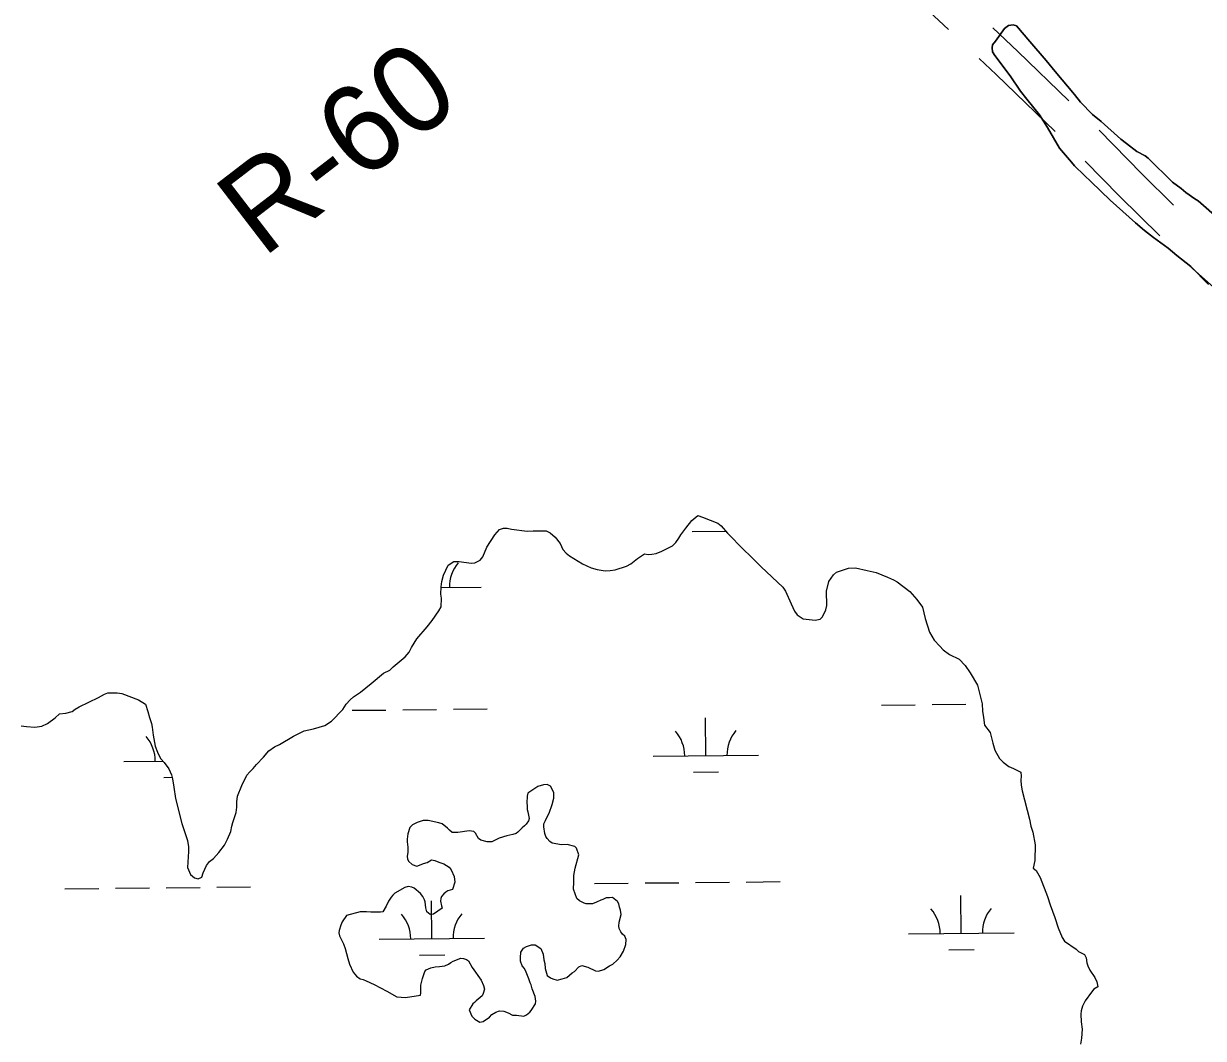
# Model space of a CAD drawing. Extents: x 3146026 to 3183936, y 897894 to 923344.
# Drawn here: x 3169411 to 3170529, y 912955 to 913917 of the extents above; entities that cross this region are included whole.
import ezdxf

# ---------------------------------------------------------------- set-up
doc = ezdxf.new("R2010")
doc.units = 0
for name, color, linetype in [('V-RIVR-RANG-IDEN', 7, 'Continuous'), ('V-ROAD-CNTR', 7, 'Continuous'), ('V-SITE-VEGE', 7, 'Continuous'), ('V-WETL-SWMP', 7, 'Continuous')]:
    doc.layers.add(name, color=color, linetype=linetype)

msp = doc.modelspace()

# ---------------------------------------------------------------- linework, layer by layer
at = {"layer": 'V-ROAD-CNTR'}
for points in [[(3170287.4, 913911.6), (3170242.1, 913954.3), (3170215.6, 913981.2)], [(3170401.7, 913844.1), (3170353.3, 913890.7), (3170329.4, 913913.2)], [(3170388.7, 913815), (3170332.6, 913869), (3170316.5, 913884.1)], [(3170500.8, 913745.2), (3170470.8, 913774.9), (3170430.2, 913816.1)], [(3170487.7, 913716), (3170449.5, 913753.7), (3170417, 913786.7)], [(3170590.8, 913621.4), (3170580.8, 913630.1), (3170519.2, 913684.7), (3170516.1, 913687.8)]]:
    msp.add_lwpolyline(points, dxfattribs=at)
at = {"layer": 'V-SITE-VEGE'}
for points in [[(3170534, 913670), (3170517.2, 913686.8), (3170503.9, 913697.3), (3170495.7, 913704.3), (3170482, 913714.4), (3170473.4, 913721.1), (3170464.8, 913728.5), (3170440.9, 913749.9), (3170422.9, 913767.1), (3170416.2, 913773.7), (3170406.8, 913782.3), (3170404.1, 913785.8), (3170392.8, 913799.1), (3170381.4, 913818.6), (3170373.9, 913830.7), (3170361.8, 913845.5), (3170355.9, 913853.3), (3170346.1, 913867.7), (3170331.3, 913886.9), (3170329.3, 913890.4), (3170328.9, 913894.3), (3170329.3, 913897), (3170332, 913900.5), (3170340.6, 913912.7), (3170344.5, 913915.4), (3170348.8, 913916.2), (3170351.9, 913915), (3170364.5, 913900.2), (3170380.1, 913882.2), (3170388.7, 913871.7), (3170407.1, 913849.9), (3170412.6, 913842.8), (3170424, 913831.1), (3170432.2, 913824.5), (3170450.9, 913807.7), (3170456.4, 913803.5), (3170466.2, 913796.1), (3170474, 913791.8), (3170476.8, 913789.8), (3170499.9, 913766.8), (3170508.1, 913761), (3170512.4, 913757.1), (3170521, 913751.2), (3170524.1, 913749.3), (3170544.8, 913731.3)], [(3170544.8, 913731.3), (3170524.1, 913749.3), (3170521, 913751.2), (3170512.4, 913757.1), (3170508.1, 913761), (3170499.9, 913766.8), (3170476.8, 913789.8), (3170474, 913791.8), (3170466.2, 913796.1), (3170456.4, 913803.5), (3170450.9, 913807.7), (3170432.2, 913824.5), (3170424, 913831.1), (3170412.6, 913842.8), (3170407.1, 913849.9), (3170388.7, 913871.7), (3170380.1, 913882.2), (3170364.5, 913900.2), (3170351.9, 913915), (3170348.8, 913916.2), (3170344.5, 913915.4), (3170340.6, 913912.7), (3170332, 913900.5), (3170329.3, 913897), (3170328.9, 913894.3), (3170329.3, 913890.4), (3170331.3, 913886.9), (3170346.1, 913867.7), (3170355.9, 913853.3), (3170361.8, 913845.5), (3170373.9, 913830.7), (3170381.4, 913818.6), (3170392.8, 913799.1), (3170404.1, 913785.8), (3170406.8, 913782.3), (3170416.2, 913773.7), (3170422.9, 913767.1), (3170440.9, 913749.9), (3170464.8, 913728.5), (3170473.4, 913721.1), (3170482, 913714.4), (3170495.7, 913704.3), (3170503.9, 913697.3), (3170517.2, 913686.8), (3170534, 913670)], [(3169969, 913088.8), (3169966, 913088.5), (3169963.1, 913088.5), (3169959.8, 913086.8), (3169957.9, 913086.2), (3169953.9, 913084.2), (3169950, 913082.9), (3169944.1, 913082.9), (3169942.2, 913083.5), (3169937.6, 913085.5), (3169935, 913087.7), (3169932, 913096.6), (3169932.3, 913103.4), (3169932.3, 913109.7), (3169933.6, 913116.5), (3169937.2, 913129.3), (3169934.9, 913135.5), (3169933.2, 913137.1), (3169926.1, 913139.1), (3169920.5, 913138.7), (3169911.7, 913140.4), (3169909.4, 913141.7), (3169907.1, 913144.6), (3169905.8, 913146.6), (3169904.8, 913149.5), (3169903.8, 913155.7), (3169903.8, 913158.7), (3169905.4, 913161.6), (3169906.4, 913163.9), (3169909, 913168.8), (3169911.9, 913177), (3169913.2, 913182.9), (3169913.5, 913188.4), (3169910.3, 913194.3), (3169907, 913196), (3169903.7, 913195.6), (3169898.2, 913194), (3169888.7, 913187.8), (3169888, 913184.8), (3169887.7, 913178.6), (3169888, 913175.6), (3169888.1, 913172.1), (3169888.7, 913170.1), (3169890, 913163.5), (3169889.4, 913161.3), (3169887.1, 913158.3), (3169885.5, 913156.7), (3169883.2, 913154.7), (3169879.3, 913150.8), (3169877.6, 913149.5), (3169874.4, 913148.5), (3169868.8, 913147.2), (3169861.6, 913144.9), (3169854.7, 913141.6), (3169850.2, 913141.6), (3169844, 913143.2), (3169842, 913144.8), (3169839, 913149.7), (3169837.4, 913151.4), (3169833.1, 913152), (3169822.4, 913150.4), (3169817.1, 913150.3), (3169814.5, 913152.6), (3169812.5, 913154.6), (3169807.6, 913158.5), (3169804.3, 913159.5), (3169794.2, 913161.7), (3169789.6, 913161.7), (3169783.7, 913159.8), (3169779.2, 913157.5), (3169776.9, 913155.2), (3169774.9, 913149), (3169774.3, 913144.1), (3169774.3, 913141.4), (3169775, 913136.5), (3169775, 913131.6), (3169774.3, 913127.7), (3169774.6, 913125.4), (3169775.6, 913123.1), (3169778.9, 913119.9), (3169783.5, 913118.6), (3169787.7, 913119.9), (3169789.7, 913120.9), (3169793.3, 913121.8), (3169797.5, 913124.5), (3169800.5, 913123.8), (3169804.4, 913122.2), (3169809, 913120.6), (3169814.2, 913117.6), (3169815.9, 913115), (3169818.8, 913108.8), (3169819.5, 913103.3), (3169817.2, 913096.4), (3169813, 913095.1), (3169811, 913093.7), (3169809, 913092.1), (3169806.8, 913089.8), (3169806.1, 913087.9), (3169805.8, 913085.2), (3169806.8, 913080.7), (3169807.4, 913078.7)], [(3169807.4, 913078.7), (3169799.3, 913072.8), (3169796, 913072.5), (3169793, 913075.1), (3169792.1, 913079), (3169791.4, 913084.6), (3169790.7, 913086.5), (3169789.1, 913089.8), (3169786.8, 913092.7), (3169780.9, 913097.6), (3169778.6, 913098.6), (3169775.3, 913099.2), (3169772.1, 913098.3), (3169762.6, 913093), (3169760.6, 913091), (3169759, 913089.1), (3169756.7, 913085.2), (3169754.4, 913080.6), (3169751.2, 913075.3), (3169748.9, 913075), (3169746.3, 913075), (3169739.7, 913075), (3169735.8, 913075.3), (3169729.6, 913075.3), (3169716.9, 913071.7), (3169712.6, 913065.8), (3169711.3, 913062.5), (3169709.7, 913057.6), (3169709.4, 913055.3), (3169710.3, 913052.4), (3169714, 913044.8), (3169715.6, 913040.3), (3169717.9, 913030.8), (3169719.5, 913025.6), (3169723.2, 913018), (3169726.4, 913014.1), (3169729.7, 913011.8), (3169732.7, 913010.9), (3169735.3, 913009.6), (3169743.1, 913006.3), (3169754.9, 913000.1), (3169764.4, 912994.6), (3169772.6, 912993.9), (3169787, 912996.2), (3169787.3, 912998.5), (3169787.3, 913005.7), (3169788.9, 913011.9), (3169790.9, 913018.5), (3169792.2, 913020.1), (3169796.7, 913022.1), (3169800.7, 913023.1), (3169804.9, 913023.4), (3169810.1, 913024.1), (3169813.4, 913025.4), (3169815.7, 913027), (3169818, 913028.3), (3169825.2, 913031.3), (3169827.8, 913031), (3169830.7, 913030), (3169832.4, 913028.7), (3169836, 913022.5), (3169844.5, 913010.4), (3169846.8, 913005.2), (3169847.5, 913001.9), (3169846.5, 912997.7), (3169845.5, 912995.4), (3169839.6, 912990.8), (3169838, 912989.1), (3169836.4, 912987.8), (3169833.1, 912982.3), (3169835.7, 912976.4), (3169838.4, 912973.4), (3169843.3, 912970.5), (3169846.5, 912971.2), (3169852.4, 912975.4), (3169854.7, 912977.7), (3169858.3, 912980), (3169861.9, 912981.3), (3169865.8, 912981), (3169870.1, 912979.4), (3169874.3, 912977.1), (3169877.9, 912977.1), (3169884.8, 912976.1), (3169887.4, 912977.4), (3169890.7, 912980.1), (3169892, 912981.7), (3169895.9, 912987.9), (3169896.2, 912990.5), (3169895.6, 912994.8), (3169892.9, 913002.3), (3169891.9, 913005.9), (3169891, 913007.9), (3169889.6, 913011.8), (3169887, 913018), (3169885.4, 913021.3), (3169883.4, 913023.9), (3169881.8, 913028.5), (3169881.8, 913031.4), (3169882.1, 913037), (3169884.7, 913040.6), (3169887.3, 913042.2)], [(3169887.3, 913042.2), (3169892.2, 913043.8), (3169895.5, 913043.9), (3169901, 913040.3), (3169903.3, 913035), (3169904, 913029.8), (3169904.7, 913026.2), (3169905, 913021.3), (3169907, 913014.8), (3169910.2, 913012.5), (3169912.5, 913011.5), (3169916.5, 913010.5), (3169921.4, 913011.5), (3169925.6, 913012.8), (3169930.8, 913017.4), (3169932.8, 913018.7), (3169937, 913023), (3169940, 913024.3), (3169945.5, 913022.7), (3169952.7, 913019.1), (3169955.7, 913018.8), (3169960.6, 913020.4), (3169966.2, 913024), (3169969.4, 913025.7), (3169973.3, 913029.3), (3169976.3, 913032.5), (3169979.5, 913037.8), (3169981.5, 913044.3), (3169981.8, 913048.9), (3169980.8, 913052.2), (3169978.5, 913054.1), (3169976.9, 913056.1), (3169975.2, 913059.4), (3169974.9, 913061.7), (3169975.2, 913065.3), (3169977.2, 913072.5), (3169976.5, 913076.7), (3169975.5, 913079.6), (3169974.9, 913082.9), (3169973.6, 913084.9), (3169969, 913088.8)]]:
    msp.add_lwpolyline(points, dxfattribs=at)
at = {"layer": 'V-WETL-SWMP'}
for p, q in [((3170044.5, 913435.6), (3170076.5, 913435.9)), ((3169806.4, 913382.5), (3169844.4, 913382.9)), ((3170224, 913271.2), (3170256, 913271.5)), ((3170272, 913271.7), (3170304, 913272)), ((3169722.2, 913266.2), (3169754.2, 913266.5)), ((3169770.2, 913266.7), (3169802.2, 913267)), ((3169818.1, 913267.2), (3169850.1, 913267.5)), ((3170057.4, 913223.1), (3170057.1, 913259.1)), ((3169505.6, 913217.6), (3169542.7, 913218)), ((3170007.4, 913222.6), (3170107.4, 913223.6)), ((3170045.6, 913207.6), (3170069.6, 913207.8)), ((3169543.7, 913202.6), (3169551.4, 913202.7)), ((3170047.8, 913103), (3170079.8, 913103.3)), ((3170095.8, 913103.4), (3170127.8, 913103.8)), ((3169449.9, 913097), (3169481.9, 913097.3)), ((3169497.9, 913097.5), (3169529.9, 913097.8)), ((3169545.9, 913098), (3169577.9, 913098.3)), ((3169593.9, 913098.4), (3169625.9, 913098.8)), ((3169951.8, 913102), (3169983.8, 913102.3)), ((3169999.8, 913102.5), (3170031.8, 913102.8)), ((3169797.7, 913049.7), (3169797.4, 913085.7)), ((3170299.6, 913054.7), (3170299.2, 913090.7)), ((3169747.7, 913049.2), (3169847.7, 913050.2)), ((3170249.6, 913054.2), (3170349.6, 913055.2)), ((3170287.8, 913039.2), (3170311.8, 913039.4)), ((3169785.9, 913034.2), (3169809.9, 913034.4))]:
    msp.add_line(p, q, dxfattribs=at)
for points in [[(3169730.2, 913283.5), (3169740.2, 913291.5), (3169752, 913301.4), (3169758, 913304.3), (3169761.1, 913307.4), (3169772.3, 913316.9), (3169776.2, 913321.4), (3169778.5, 913325.8), (3169783.4, 913334), (3169793.2, 913345.5), (3169797.9, 913351.3), (3169804.3, 913360.6), (3169806.5, 913364.2), (3169806.8, 913372.4), (3169806.3, 913376.4), (3169806.4, 913383.3), (3169807.2, 913388.3), (3169808.8, 913394.4), (3169813.1, 913403.7), (3169818.4, 913407.2), (3169823.5, 913407.4), (3169835.1, 913405.8), (3169838.6, 913406), (3169843.5, 913408.7), (3169846, 913411.8), (3169849.8, 913420.9), (3169857.5, 913432.7), (3169861.8, 913437.5), (3169865.5, 913438.9), (3169869.1, 913438.9), (3169873.3, 913438), (3169888.2, 913436.2), (3169893.8, 913436.4), (3169906.2, 913436.5), (3169910, 913434.5), (3169914.6, 913430.5), (3169919.2, 913424.5), (3169921.9, 913418.8), (3169925, 913415.2), (3169928.1, 913412.8), (3169940.5, 913405.2), (3169948.7, 913401.4), (3169954.3, 913399.6), (3169962.1, 913398.5), (3169966.9, 913398.7), (3169971.6, 913399.5), (3169982.1, 913402.9), (3169986.5, 913405.1), (3169992.7, 913410), (3169999.2, 913414.4), (3170002.7, 913413.9), (3170006.1, 913414.1), (3170010.3, 913414.8), (3170015.8, 913417), (3170025.8, 913422.1), (3170028.9, 913425.2), (3170031.9, 913429.4), (3170033.9, 913432.5), (3170038.5, 913438.9), (3170044.3, 913446.3), (3170049.9, 913450.9), (3170054.3, 913449.4), (3170068.8, 913443.5), (3170072.1, 913441.1), (3170078, 913434.2), (3170093.4, 913418.4), (3170099.5, 913412.8), (3170110, 913402.1), (3170130.4, 913383), (3170133, 913379.2), (3170138.3, 913367), (3170141.4, 913360.3), (3170143.9, 913356.8), (3170149.6, 913353), (3170161.1, 913351.6), (3170165.8, 913352.5), (3170168.1, 913354.7), (3170171.2, 913361.4), (3170172.1, 913365.6), (3170171.9, 913379.2), (3170174.1, 913388.2), (3170178.6, 913394.7), (3170181.3, 913397.3), (3170192.6, 913401.1), (3170199.2, 913401.3), (3170210.5, 913398.6), (3170218.8, 913397), (3170229.7, 913392.4), (3170235.4, 913389.9), (3170238.7, 913388.1), (3170250.7, 913379), (3170257.4, 913371.4), (3170262.7, 913363.9), (3170265.3, 913353.2), (3170269.5, 913340.3), (3170273.9, 913332.7), (3170279.2, 913326.9), (3170282.6, 913323.6), (3170288.5, 913319.2), (3170297.7, 913314.7), (3170303.4, 913308.7)], [(3170303.4, 913308.7), (3170308.1, 913301.8), (3170314.9, 913290.2), (3170319.3, 913272.4), (3170319.7, 913265.4), (3170320.8, 913259.4), (3170321.5, 913252), (3170327, 913245.1), (3170328.4, 913240.2), (3170329.5, 913235.1), (3170331.4, 913228.3), (3170335.7, 913220.5), (3170339.2, 913217.1), (3170344.8, 913213.1), (3170349.2, 913211.1), (3170356, 913207.5), (3170356.3, 913203.8), (3170356, 913200), (3170356.3, 913195.3), (3170357.3, 913189.8), (3170364.4, 913163.1), (3170365.7, 913156.5), (3170367.3, 913150.7), (3170369.7, 913138.7), (3170369.2, 913123.8), (3170367.9, 913116.5), (3170370.5, 913114.4), (3170374.5, 913107.8), (3170381.4, 913089.8), (3170384, 913081.8), (3170388.4, 913069.8), (3170391.5, 913060), (3170395.2, 913050.7), (3170397.5, 913047.3), (3170408.6, 913039.8), (3170410.8, 913037.7), (3170416.3, 913034.7), (3170417.9, 913031.7), (3170418.5, 913026.9), (3170419.6, 913024), (3170421.6, 913020), (3170426.1, 913012.9), (3170428.2, 913008.9), (3170429.1, 913004.2), (3170425.3, 913001.7), (3170423.1, 912998.9), (3170417.1, 912990.7), (3170414.6, 912985.6), (3170413.3, 912981.4), (3170412.9, 912978.3), (3170413.3, 912970.9), (3170414.2, 912963.8), (3170413.7, 912955.4), (3170412.8, 912949.8)], [(3169408.4, 913251.5), (3169413.5, 913250.8), (3169421.2, 913250.2), (3169428.1, 913251.2), (3169433.2, 913253.7), (3169440.6, 913259), (3169444.8, 913263), (3169450.8, 913263.4), (3169456.6, 913265.2), (3169459.7, 913267.4), (3169463.2, 913269.4), (3169481.7, 913278.4), (3169487.2, 913281.5), (3169490.6, 913282.7), (3169499.3, 913282.8), (3169503.9, 913282.2), (3169519.7, 913276.2), (3169526.3, 913271.9), (3169528.3, 913265), (3169530.1, 913259.5), (3169531.8, 913253.7), (3169532.5, 913250.1), (3169533.4, 913242.8), (3169535.3, 913232.3), (3169537.5, 913226.4), (3169539.1, 913223.2), (3169540.9, 913220.1), (3169543.8, 913216.6), (3169548.4, 913210.8), (3169550.8, 913205.2), (3169551.7, 913201.2), (3169553.2, 913193.4), (3169554.6, 913182.6), (3169560.7, 913159), (3169566, 913142.8), (3169567.1, 913136.8), (3169567.1, 913132.4), (3169566, 913117.3), (3169568.8, 913110.4), (3169572.6, 913107.5), (3169576.2, 913106.6), (3169579.7, 913108.1), (3169581, 913112.1), (3169583.9, 913119), (3169586.9, 913123), (3169590.6, 913125.6), (3169595.7, 913131.4), (3169601.1, 913138.5), (3169604, 913144), (3169607.1, 913151.4), (3169608.2, 913156.5), (3169609.1, 913159.8), (3169612.3, 913169.4), (3169612.9, 913174.4), (3169612.9, 913179.4), (3169613.6, 913184.9), (3169617.6, 913194.9), (3169622.3, 913204.6), (3169625.2, 913207.8), (3169628.4, 913211.1), (3169631.4, 913214.8), (3169638.1, 913221.7), (3169643.2, 913227.9), (3169648.6, 913231.5), (3169653.2, 913233.9), (3169666.4, 913241.8), (3169676.8, 913246.7), (3169685.5, 913248.5), (3169696.1, 913251.8), (3169702.6, 913256), (3169713.3, 913267.1), (3169716.6, 913271.9), (3169720.4, 913276.2), (3169723.3, 913279), (3169730.2, 913283.5)]]:
    msp.add_lwpolyline(points, dxfattribs=at)
for centre, start, end in [((3169849.6, 913383.4), 139.7992, 181.3429), ((3169500.3, 913218.1), 359.7992, 41.3429), ((3170002.2, 913223.1), 359.7992, 41.3429), ((3170112.7, 913224.2), 139.7992, 181.3429), ((3169742.5, 913049.6), 359.7992, 41.3429), ((3169853, 913050.7), 139.7992, 181.3429), ((3170244.4, 913054.6), 359.7992, 41.3429), ((3170354.8, 913055.7), 139.7992, 181.3429)]:
    msp.add_arc(centre, 35.2, start, end, dxfattribs=at)

# ---------------------------------------------------------------- texts
at = {"layer": 'V-RIVR-RANG-IDEN'}
msp.add_text('R-60  ', height=83, rotation=37.5232, dxfattribs=at).set_placement((3169637.3, 913694.3))

doc.saveas('drawing.dxf')
